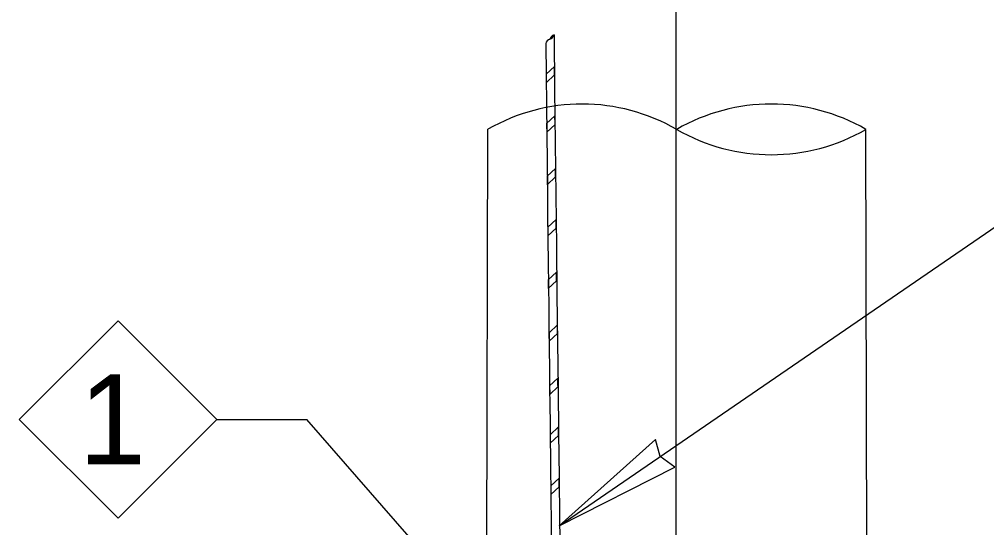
# Model space of a CAD drawing. Extents: x 99862 to 103151, y 100000 to 102076.
# Drawn here: x 100265.4 to 100437.4, y 101888.4 to 101978.8 of the extents above; entities that cross this region are included whole.
import ezdxf

# ---------------------------------------------------------------- set-up
doc = ezdxf.new("R2010")
doc.units = 0
for name, color, linetype in [('Level 1', 7, 'Continuous'), ('Level 15', 7, 'Continuous'), ('Level 20', 7, 'Continuous'), ('Level 4', 7, 'Continuous'), ('Level 8', 7, 'Continuous')]:
    doc.layers.add(name, color=color, linetype=linetype)

msp = doc.modelspace()

# ---------------------------------------------------------------- linework, layer by layer
at = {"layer": 'Level 1'}
for centre, radius, start, end in [((100365.47, 101930.09), 33.63, 60, 119.9106), ((100399.1, 101930.09), 33.64, 60.0028, 120.0028), ((100399.1, 101988.35), 33.63, 240, 300.0057)]:
    msp.add_arc(centre, radius, start, end, dxfattribs=at)
at = {"layer": 'Level 15'}
for p, q in [((100361.4, 101888.7), (100555.85, 102022.24)), ((100382.17, 101307.99), (100382.17, 102008.07)), ((100300.5, 101907.64), (100316.5, 101907.64)), ((100376.12, 101839.42), (100316.5, 101907.64))]:
    msp.add_line(p, q, dxfattribs=at)
msp.add_lwpolyline([(100361.4, 101888.7), (100381.91, 101899.16), (100379.35, 101901.02), (100378.53, 101904.08)], close=True, dxfattribs=at)
at = {"layer": 'Level 20'}
msp.add_lwpolyline([(100282.95, 101925.19), (100300.5, 101907.64), (100282.95, 101890.09), (100265.39, 101907.64)], close=True, dxfattribs=at)
at = {"layer": 'Level 4'}
for p, q in [((100348.42, 101827.42), (100348.7, 101959.25)), ((100416.15, 101827.42), (100415.92, 101959.22))]:
    msp.add_line(p, q, dxfattribs=at)
at = {"layer": 'Level 8'}
for p, q in [((100360.53, 101970.43), (100359.05, 101969.05)), ((100359.07, 101967.53), (100360.55, 101968.91)), ((100360.62, 101961.62), (100359.14, 101960.24)), ((100359.16, 101958.72), (100360.64, 101960.1)), ((100360.72, 101952.28), (100359.24, 101950.9)), ((100359.26, 101949.38), (100360.74, 101950.76)), ((100360.84, 101943.2), (100359.36, 101941.82)), ((100359.38, 101940.3), (100360.86, 101941.68)), ((100360.9, 101933.83), (100359.42, 101932.45)), ((100359.44, 101930.93), (100360.92, 101932.31)), ((100361.06, 101924.44), (100359.58, 101923.06)), ((100359.59, 101921.54), (100361.08, 101922.92)), ((100361.14, 101914.99), (100359.67, 101913.6)), ((100359.7, 101912.09), (100361.17, 101913.47)), ((100361.24, 101906.32), (100359.77, 101904.93)), ((100359.8, 101903.41), (100361.27, 101904.8)), ((100361.35, 101897.2), (100359.88, 101895.81)), ((100359.91, 101894.29), (100361.38, 101895.68))]:
    msp.add_line(p, q, dxfattribs=at)
for points in [[(100359.05, 101969.05), (100359.05, 101969.05)], [(100359.07, 101967.53), (100359.07, 101967.53)], [(100359.16, 101958.72), (100359.16, 101958.72)], [(100359.24, 101950.9), (100359.24, 101950.9)], [(100359.38, 101940.3), (100359.38, 101940.3)], [(100359.42, 101932.45), (100359.42, 101932.45)], [(100359.44, 101930.93), (100359.44, 101930.93)], [(100359.58, 101923.06), (100359.58, 101923.06)], [(100359.59, 101921.54), (100359.59, 101921.54)], [(100359.67, 101913.6), (100359.67, 101913.6)], [(100359.77, 101904.93), (100359.77, 101904.93)], [(100359.8, 101903.41), (100359.8, 101903.41)], [(100359.88, 101895.81), (100359.88, 101895.81)], [(100359.91, 101894.29), (100359.91, 101894.29)]]:
    msp.add_lwpolyline(points, dxfattribs=at)
for centre, start, end in [((100360.04, 101974.22), 106.7524, 166.7524), ((100360.78, 101975.01), 106.7524, 166.7524), ((100359.41, 101976.29), 286.7524, 346.7524)]:
    msp.add_arc(centre, 1.08, start, end, dxfattribs=at)
for points, degree in [([(100360.46, 101976.04), (100362.77, 101764.47), (100364.86, 101716.55), (100361.13, 101710.61), (100357.53, 101709.52), (100356.79, 101709.42)], 3), ([(100358.99, 101974.47), (100359.65, 101913.81), (100360.2, 101868.8), (100361.31, 101785.38), (100361.73, 101760.43), (100362.04, 101739.44), (100362.08, 101735.18), (100362.07, 101731.13), (100362.07, 101730.38), (100362.05, 101728.96), (100362.04, 101728.28), (100361.99, 101726.31), (100361.95, 101725.1), (100361.78, 101721.77), (100361.62, 101719.94), (100361.21, 101716.92), (100360.97, 101715.73), (100360.42, 101713.9), (100360.13, 101713.25), (100359.54, 101712.32), (100359.26, 101712.04), (100358.84, 101711.72), (100358.72, 101711.65), (100358.59, 101711.57)], 3), ([(100360.55, 101968.91), (100360.55, 101969.42), (100360.54, 101969.92), (100360.53, 101970.43)], 2), ([(100359.05, 101969.05), (100359.06, 101968.29), (100359.07, 101967.53)], 2), ([(100360.64, 101960.1), (100360.64, 101960.61), (100360.63, 101961.12), (100360.62, 101961.62)], 2), ([(100359.14, 101960.24), (100359.15, 101959.48), (100359.16, 101958.72)], 2), ([(100360.74, 101950.76), (100360.73, 101951.27), (100360.72, 101951.78), (100360.72, 101952.28)], 2), ([(100359.24, 101950.9), (100359.25, 101950.14), (100359.26, 101949.38)], 2), ([(100360.86, 101941.68), (100360.85, 101942.19), (100360.85, 101942.7), (100360.84, 101943.2)], 2), ([(100359.36, 101941.82), (100359.37, 101941.06), (100359.38, 101940.3)], 2), ([(100360.92, 101932.31), (100360.91, 101932.82), (100360.91, 101933.33), (100360.9, 101933.83)], 2), ([(100359.42, 101932.45), (100359.43, 101931.69), (100359.44, 101930.93)], 2), ([(100361.08, 101922.92), (100361.07, 101923.43), (100361.07, 101923.93), (100361.06, 101924.44)], 2), ([(100359.58, 101923.06), (100359.59, 101922.3), (100359.59, 101921.54)], 2), ([(100361.17, 101913.47), (100361.16, 101913.98), (100361.15, 101914.48), (100361.14, 101914.99)], 2), ([(100359.67, 101913.6), (100359.69, 101912.84), (100359.7, 101912.09)], 2), ([(100361.27, 101904.8), (100361.26, 101905.31), (100361.25, 101905.81), (100361.24, 101906.32)], 2), ([(100359.77, 101904.93), (100359.79, 101904.17), (100359.8, 101903.41)], 2), ([(100361.38, 101895.68), (100361.37, 101896.18), (100361.36, 101896.69), (100361.35, 101897.2)], 2), ([(100359.88, 101895.81), (100359.9, 101895.05), (100359.91, 101894.29)], 2)]:
    msp.add_open_spline(points, degree=degree, dxfattribs=at)

# ---------------------------------------------------------------- texts
at = {"layer": 'Level 20'}
msp.add_text('1', height=16, dxfattribs=at).set_placement((100276, 101899.64))

doc.saveas('drawing.dxf')
